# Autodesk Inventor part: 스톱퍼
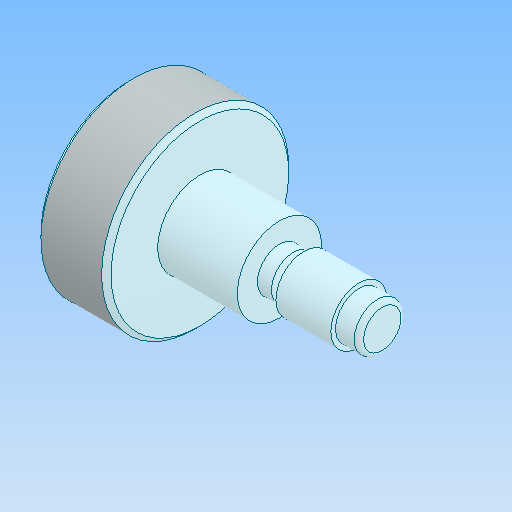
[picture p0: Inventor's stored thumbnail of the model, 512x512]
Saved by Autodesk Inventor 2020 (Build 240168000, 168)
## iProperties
Created: 2024-07
Part Number: 스톱퍼
Material: 강철, 탄소
Document SubType Name: Modeling
Designer: oem
Density: 7.85 g/cm^3
Appearance: 기본값
Author: jhkim
Sending System: Autodesk Inventor 2025
Preprocessor: ST-DEVELOPER v20
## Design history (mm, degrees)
feature "솔리드1"
node "솔리드2"
